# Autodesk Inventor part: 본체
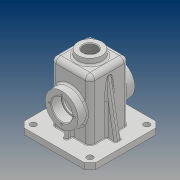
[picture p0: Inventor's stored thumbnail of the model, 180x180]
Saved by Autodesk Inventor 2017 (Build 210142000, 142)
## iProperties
Part Number: 본체
Material: 일반
Document SubType Name: Modeling
Designer: 20
Density: 1 g/cm^3
Appearance: 기본값
Mass: 293.223 g
Surface Area: 897.811 cm^2
Volume: 293.223 cm^3
Author: 20
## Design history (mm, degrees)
sketch "스케치1"
  geometry: L1 (-32.5, 32.5)-(32.5, 32.5); L2 (32.5, 32.5)-(32.5, -32.5); L3 (32.5, -32.5)-(-32.5, -32.5); L4 (-32.5, -32.5)-(-32.5, 32.5); L5 (-32.5, 32.5)-(32.5, -32.5); L6 (32.5, 32.5)-(-32.5, -32.5); 1 further point
  constraints: 12 end point, 2 midpoint, 2 parallel, 1 horizontal, 1 perpendicular
  dimensions: "d0" = 65 distance of L2.end L3.end; "d1" = 65 distance of L1.end L2.end
extrude "돌출1" new body sketch "스케치1" distance "d2" = 110; taper "d3" = 0 deg
sketch "스케치2"
  geometry: L1 (-27.5, -27.5)-(27.5, -27.5); L2 (27.5, -27.5)-(27.5, 27.5); L3 (27.5, 27.5)-(-27.5, 27.5); L4 (-27.5, 27.5)-(-27.5, -27.5); L5 (-27.5, -27.5)-(27.5, 27.5); L6 (27.5, -27.5)-(-27.5, 27.5); 1 further point
  constraints: 12 end point, 2 midpoint, 2 parallel, 1 horizontal, 1 perpendicular
  dimensions: "d4" = 55 distance of L3.end L2.end; "d5" = 55 distance of L2.end L1.end
extrude "돌출2" cut sketch "스케치2" distance "d6" = 105; taper "d7" = 0 deg
sketch "스케치3"
  geometry: L1 (-60, -60)-(60, -60); L2 (60, -60)-(60, 60); L3 (60, 60)-(-60, 60); L4 (-60, 60)-(-60, -60); L5 (-60, -60)-(60, 60); L6 (60, -60)-(-60, 60); L7 (-32.5, 32.5)-(-32.5, -32.5) reference; L8 (-32.5, -32.5)-(32.5, -32.5) reference; L9 (32.5, -32.5)-(32.5, 32.5) reference; L10 (32.5, 32.5)-(-32.5, 32.5) reference; 1 further point
  constraints: 12 end point, 2 midpoint, 2 parallel, 1 horizontal, 1 perpendicular
  dimensions: "d8" = 120 distance of L3.end L2.end; "d9" = 120 distance of L2.end L1.end
extrude "돌출3" join sketch "스케치3" distance "d10" = 10; taper "d11" = 0 deg
sketch "스케치4"
  geometry: C1 r 20 at (0, 0); 1 further point
  constraints: 1 centre point, 1 coincident
  dimensions: "d12" = 40 diameter of C1
extrude "돌출4" join sketch "스케치4" distance "d13" = 10; taper "d14" = 0 deg
feature "면 기울기2" dims angle "d105" = 5 deg
sketch "스케치5"
  geometry: L1 (92.5, -110)-(-27.5, -110) reference; C1 r 27.5 at (32.5, -55); 2 further points
  constraints: 1 centre point, 1 midpoint, 1 vertical alignment
  dimensions: "d16" = 55 diameter of C1; "d17" = 55 distance from line of L1 C1.centre
extrude "돌출5" join sketch "스케치5" distance "d18" = 15; taper "d19" = 0 deg
sketch "스케치6"
  geometry: C1 r 27.5 at (0, 0) reference; C2 r 17.5 at (0, 0); 1 further point
  constraints: 1 centre point, 1 coincident
  dimensions: "d20" = 35 diameter of C2
extrude "돌출6" cut sketch "스케치6" distance "d21" = 17; taper "d22" = 0 deg
sketch "스케치7"
  geometry: C1 r 17.5 at (0, 0) reference; C2 r 15 at (0, 0); 1 further point
  constraints: 1 centre point, 1 coincident
  dimensions: "d23" = 30 diameter of C2
extrude "돌출7" cut sketch "스케치7" distance "d24" = 3; taper "d25" = 0 deg
sketch "스케치8" dims "d26" = 42
  geometry: L1 (60, -55)-(-60, -55) reference; C1 r 15 at (0, 0) reference; 4 further points
  constraints: 2 vertical alignment, 1 coincident, 1 midpoint, 2 other
hole "구멍1" sketch "스케치8" at (0, 21) diameter "d27" = 3.242; stored, may be unused: countersink angle "d31" = 90 deg, drill point angle "d33" = 118 deg; dims "d28" = 8, "d29" = 4, "d30" = 2, "d32" = 10
sketch "스케치9"
  geometry: L1 (-42.5, 9.836)-(-42.5, 24.836); L2 (60, 10)-(-60, 10) reference; L3 (-27.5, 0)-(-27.5, 105) reference; 1 further point
  constraints: 2 end point, 1 vertical
  dimensions: "d37" = 15 distance between parallel lines of L1 L3; "d38" = 15 distance of L1.start L1.end
feature "리브1" sketch "스케치9" dims "d39" = 1, "d40" = 6, "d41" = 0, "d42" = 0, "d43" = 1, "d44" = 1
sketch "스케치11"
  geometry: L1 (60, 10)-(-60, 10) reference; L2 (42.5, 10)-(42.5, 25); L3 (27.5, 0)-(27.5, 105) reference; 1 further point
  constraints: 2 end point, 1 point on line, 1 vertical
  dimensions: "d45" = 15 distance between parallel lines of L3 L2; "d46" = 15 distance of L2.start L2.end
feature "리브2" sketch "스케치11" dims "d47" = 1, "d48" = 6, "d49" = 0, "d50" = 0, "d51" = 1, "d52" = 1
sketch "스케치12"
  geometry: L1 (-60, 10)-(60, 10) reference; L2 (-48, 10)-(-37.581, 69.088); L3 (-60, 0)-(-60, 10) reference; 1 further point
  constraints: 2 end point, 1 point on line
  dimensions: "d53" = 12 distance from line of L2.start L3; "d54" = 10 deg angle of L3 L2; "d55" = 60 distance of L2.start L2.end
feature "리브3" sketch "스케치12" dims "d56" = 1, "d57" = 10, "d58" = 0, "d59" = 0, "d60" = 1, "d61" = 1
hole "구멍2" diameter "d64" = 22.835; stored, may be unused: countersink angle "d68" = 90 deg, drill point angle "d70" = 118 deg; dims "d62" = 10, "d63" = 10, "d65" = 50, "d66" = 4, "d67" = 2, "d69" = 30
sketch "스케치13"
  geometry: L1 (-60, 60)-(-60, -60) reference; L2 (60, 60)-(-60, 60) reference; C1 r 5 at (-47.5, 47.5); 1 further point
  constraints: 1 centre point
  dimensions: "d71" = 10 diameter of C1; "d72" = 12.5 distance from line of C1.centre L1; "d73" = 12.5 distance from line of L2 C1.centre
extrude "돌출8" cut sketch "스케치13" stored distance "d74" = 3; taper "d75" = 0 deg
chamfer "모따기1" distance "d82" = 10; stored, may be unused: second distance "d83" = 2, angle "d84" = 45 deg
chamfer "모따기2" distance "d85" = 1; stored, may be unused: second distance "d86" = 2, angle "d87" = 45 deg
fillet "모깎기1" dims "d88" = 0.3
fillet "모깎기2" dims "d89" = 3
fillet "모깎기3" dims "d90" = 3
fillet "모깎기4" dims "d91" = 8
fillet "모깎기5" dims "d92" = 8
fillet "모깎기7" dims "d94" = 3
fillet "모깎기8" dims "d95" = 3
fillet "모깎기9" dims "d96" = 3
fillet "모깎기10" dims "d97" = 3
fillet "모깎기12" dims "d99" = 1
node "작업 평면1"
sketch "스케치14"
  geometry: L1 (57, 0)-(57, 91) reference; L2 (4.5, -18)-(44.5, -18) reference; 2 further points
  constraints: 1 other
  dimensions: "d101" = 32.5 distance from line of point (24.5, 8) L1; "d102" = 26 distance from line of point (24.5, 8) L2
feature "엠보싱1" sketch "스케치14" dims "d8" = 120, "d9" = 120, "d103" = 0.5, "d104" = 0
fillet "모깎기13" dims "d106" = 3
node "솔리드1"
pattern_circular "원형 패턴1" dims angle "d35" = 360 deg
mirror "미러1"
mirror "미러2"
pattern_linear "직사각형 패턴1" dims "d78" = 95, "d81" = 95
